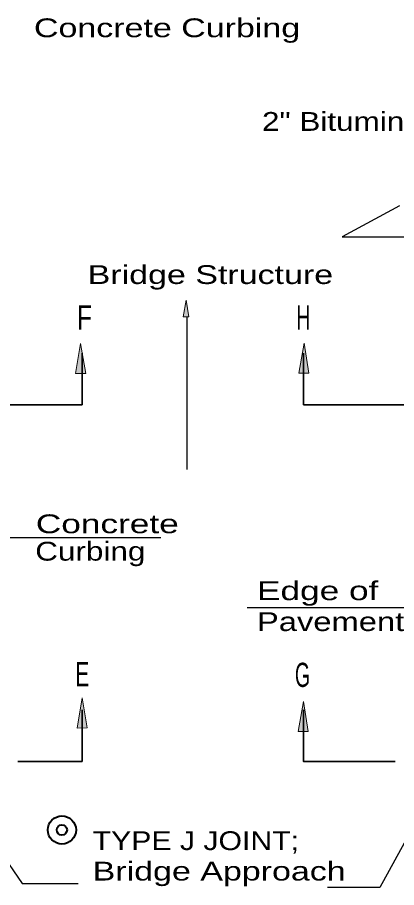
# Model space of a CAD drawing. Extents: x 14 to 49.3, y 28 to 50.
# Drawn here: x 22.75 to 25.57, y 32.8 to 39.28 of the extents above; entities that cross this region are included whole.
import ezdxf

# ---------------------------------------------------------------- set-up
doc = ezdxf.new("R2010")
doc.units = 0
doc.header["$LTSCALE"] = 0.056
doc.layers.add('3', color=7, linetype='Continuous', lineweight=13)
doc.layers.add('5', color=7, linetype='Continuous', lineweight=35)

msp = doc.modelspace()

# ---------------------------------------------------------------- hatches: boundary and pattern name
at = {"layer": '3'}
for points in [[(23.98058, 37.04717), (24.02225, 37.04717), (24.00142, 37.17217), (24.00142, 37.17217)], [(23.18, 36.62458), (23.25483, 36.62525), (23.216, 36.84925), (23.216, 36.84925)], [(24.91533, 36.62733), (24.8405, 36.628), (24.87933, 36.852), (24.87933, 36.852)], [(23.19183, 33.98467), (23.26667, 33.98533), (23.22783, 34.20933), (23.22783, 34.20933)], [(24.91092, 33.95867), (24.83608, 33.95933), (24.87492, 34.18333), (24.87492, 34.18333)]]:
    msp.add_hatch(color=256, dxfattribs=at).paths.add_polyline_path(points)

# ---------------------------------------------------------------- linework, layer by layer
at = {"layer": '3', "lineweight": 25}
for p, q in [((24.0075, 37.04725), (24.0075, 35.90958)), ((22.23075, 35.40483), (23.81375, 35.40483)), ((26.55275, 34.88042), (24.45583, 34.88042))]:
    msp.add_line(p, q, dxfattribs=at)
for points in [[(25.58925, 37.8735), (25.16392, 37.64425), (25.68642, 37.64425)], [(25.91625, 33.66042), (25.44375, 32.79608), (25.05367, 32.79608)], [(22.28233, 33.55725), (22.783, 32.82575), (23.19808, 32.82575)]]:
    msp.add_lwpolyline(points, dxfattribs=at)
at = {"layer": '3'}
for points in [[(23.98058, 37.04717), (24.02225, 37.04717), (24.00142, 37.17217), (24.00142, 37.17217)], [(23.18, 36.62458), (23.25483, 36.62525), (23.216, 36.84925), (23.216, 36.84925)], [(24.91533, 36.62733), (24.8405, 36.628), (24.87933, 36.852), (24.87933, 36.852)], [(23.19183, 33.98467), (23.26667, 33.98533), (23.22783, 34.20933), (23.22783, 34.20933)], [(24.91092, 33.95867), (24.83608, 33.95933), (24.87492, 34.18333), (24.87492, 34.18333)]]:
    msp.add_lwpolyline(points, close=True, dxfattribs=at)
at = {"layer": '3', "lineweight": 40}
for radius in [0.10473, 0.03808]:
    msp.add_circle((23.07808, 33.22525), radius, dxfattribs=at)
at = {"layer": '5'}
for p, q in [((23.22925, 36.777), (23.22925, 36.39083)), ((24.87575, 36.777), (24.87575, 36.39083)), ((22.5485, 36.39083), (23.22925, 36.39083)), ((24.87575, 36.39083), (25.67525, 36.39083)), ((23.22925, 34.121), (23.22925, 33.73483)), ((22.74883, 33.73483), (23.22925, 33.73483))]:
    msp.add_line(p, q, dxfattribs=at)
msp.add_lwpolyline([(24.87575, 34.121), (24.87575, 33.73483), (25.55642, 33.73483)], dxfattribs=at)

# ---------------------------------------------------------------- texts
at = {"layer": '3'}
for s, width, p in [('Concrete Curbing', 1.35, (22.86992, 39.13)), ('2" Bituminous Overlay', 1.25, (24.5665, 38.4325)), ('Bridge Structure', 1.35, (23.2695, 37.29175)), ('Concrete', 1.4, (22.88383, 35.43558)), ('Curbing', 1.25, (22.87942, 35.2315)), ('Edge of', 1.4, (24.52908, 34.93717)), ('Pavement', 1.3, (24.52908, 34.70692)), ('TYPE J JOINT;', 1.2, (23.30667, 33.07542)), ('Bridge Approach', 1.35, (23.30667, 32.84875))]:
    msp.add_text(s, height=0.14, dxfattribs=dict(at, width=width)).set_placement(p)
at = {"layer": '5'}
for s, width, p in [('F', 0.75, (23.19083, 36.95217)), ('H', 0.6, (24.822, 36.952)), ('E', 0.65, (23.17742, 34.29617)), ('G', 0.6, (24.81158, 34.29083))]:
    msp.add_text(s, height=0.18, dxfattribs=dict(at, width=width)).set_placement(p)

doc.saveas('drawing.dxf')
